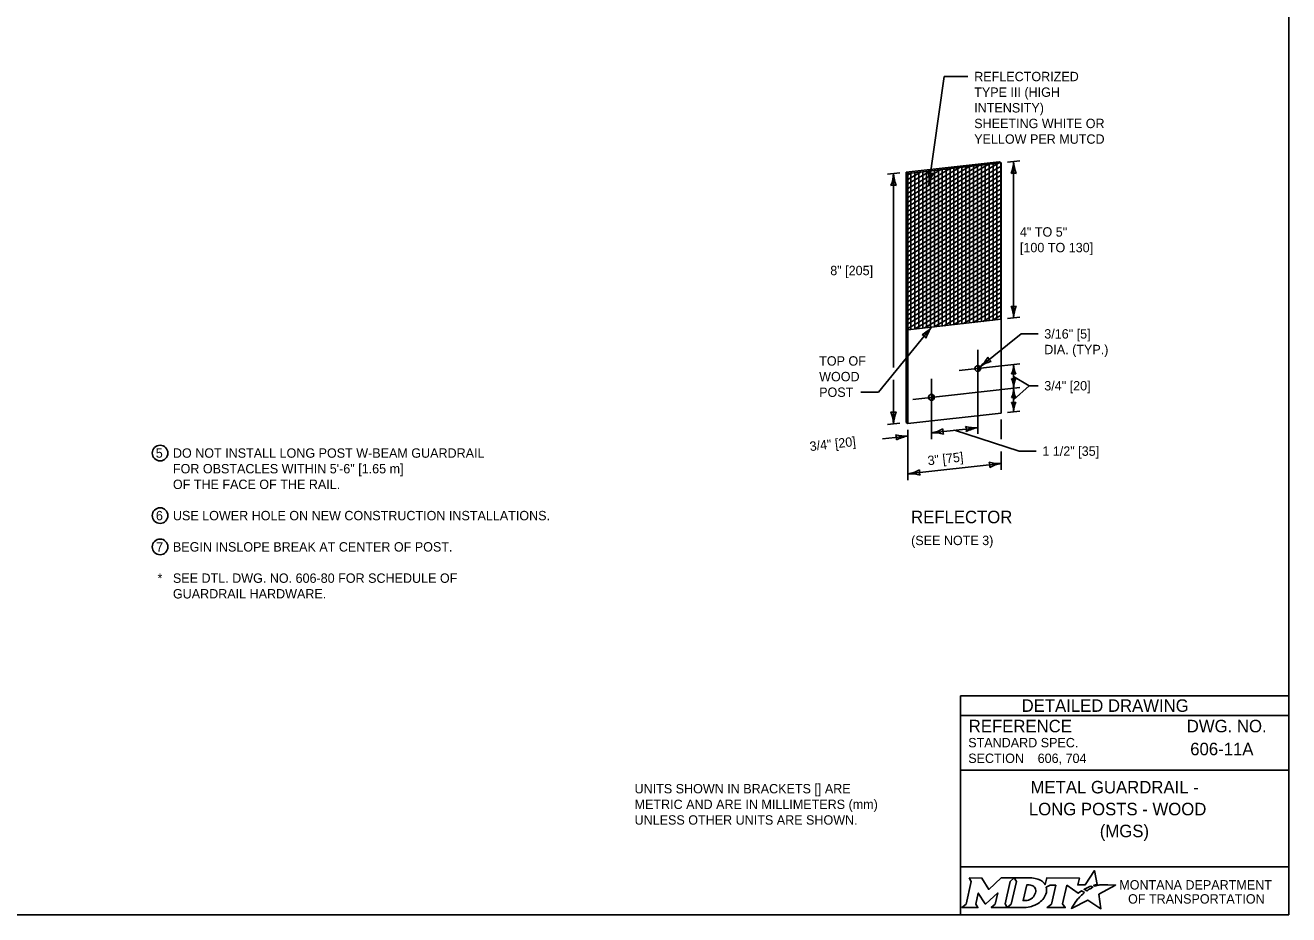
# Model space of a CAD drawing. Extents: x 49991.4 to 50021, y 49987.6 to 50011.4.
# Drawn here: x 50008.67 to 50016.75, y 49987.8 to 49993.49 of the extents above; entities that cross this region are included whole.
import ezdxf

# ---------------------------------------------------------------- set-up
doc = ezdxf.new("R2010")
doc.units = 0
for name, color, linetype in [('Default', 7, 'Continuous'), ('Level 1', 7, 'Continuous'), ('Level 2', 7, 'Continuous'), ('Level 3', 7, 'Continuous'), ('Level 5', 7, 'Continuous')]:
    doc.layers.add(name, color=color, linetype=linetype)

msp = doc.modelspace()

# ---------------------------------------------------------------- linework, layer by layer
at = {"layer": 'Default'}
for points in [[(50014.7056, 49988.0338), (50014.7197, 49988.0104), (50014.6862, 49987.8671), (50014.6605, 49987.8446), (50014.7621, 49987.8446), (50014.7486, 49987.8674), (50014.7648, 49987.9375), (50014.8085, 49987.8685), (50014.8138, 49987.8685), (50014.8889, 49987.938), (50014.8725, 49987.8669), (50014.8478, 49987.8449), (50014.9494, 49987.8449), (50014.9356, 49987.8682), (50014.9688, 49988.0106)], [(50014.9688, 49988.0106), (50014.9941, 49988.0338), (50014.9117, 49988.0338), (50014.8321, 49987.9608), (50014.7876, 49988.0335), (50014.7056, 49988.0338)], [(50015.1077, 49988.0338), (50014.9941, 49988.0338), (50015.0088, 49988.0109), (50014.9749, 49987.8671), (50014.9494, 49987.8449), (50015.06, 49987.8449)], [(50015.5126, 49987.9811), (50015.5023, 49987.9867), (50015.5139, 49987.9895), (50015.5255, 49987.9915), (50015.5081, 49988.0816), (50015.4486, 49987.9903), (50015.4013, 49987.9896), (50015.4116, 49988.0337), (50015.2024, 49988.0338), (50015.1923, 49987.9913), (50015.1865, 49987.9996)], [(50015.1317, 49987.9471), (50015.1305, 49987.939), (50015.1273, 49987.9297), (50015.1231, 49987.9215), (50015.1175, 49987.914), (50015.111, 49987.9071), (50015.1031, 49987.9008), (50015.0948, 49987.8961), (50015.0857, 49987.8922), (50015.0766, 49987.8899), (50015.0674, 49987.889), (50015.0515, 49987.889), (50015.0751, 49987.989), (50015.0911, 49987.989), (50015.0987, 49987.9884), (50015.1063, 49987.9865), (50015.1129, 49987.9835), (50015.119, 49987.9793), (50015.1238, 49987.9743), (50015.1275, 49987.9683), (50015.1302, 49987.9621), (50015.1318, 49987.9547), (50015.1318, 49987.9517), (50015.1317, 49987.9471)], [(50015.1991, 49987.9747), (50015.2237, 49987.9878), (50015.2606, 49987.9878), (50015.232, 49987.8673), (50015.2045, 49987.8446), (50015.3207, 49987.8446), (50015.3037, 49987.8675), (50015.3319, 49987.9877), (50015.4032, 49987.936), (50015.4243, 49987.9511), (50015.444, 49987.9402)], [(50015.3882, 49987.8843), (50015.3729, 49987.8599), (50015.3682, 49987.8524), (50015.3624, 49987.8438), (50015.3601, 49987.8395), (50015.4654, 49987.8926), (50015.5493, 49987.8375), (50015.5362, 49987.9302), (50015.6431, 49987.9886), (50015.5938, 49987.9894), (50015.5637, 49987.9898), (50015.5429, 49987.9901), (50015.5361, 49987.9886), (50015.5312, 49987.9874), (50015.5228, 49987.9851), (50015.5126, 49987.9811)], [(50015.4622, 49987.9535), (50015.4598, 49987.9518), (50015.4415, 49987.9614), (50015.4518, 49987.9671), (50015.4559, 49987.9693), (50015.4645, 49987.9733), (50015.4702, 49987.9759), (50015.4781, 49987.9789), (50015.4854, 49987.9816), (50015.4972, 49987.9742), (50015.4932, 49987.9721), (50015.4886, 49987.9696), (50015.4844, 49987.9674), (50015.4794, 49987.9645), (50015.4775, 49987.9634), (50015.4748, 49987.9618), (50015.4723, 49987.9604), (50015.47, 49987.9588), (50015.4674, 49987.957), (50015.4647, 49987.9552), (50015.4622, 49987.9535)], [(50015.1057, 49987.8522), (50015.1141, 49987.8548), (50015.1271, 49987.8602), (50015.1475, 49987.8712)], [(50015.4021, 49987.9004), (50015.4021, 49987.9004)]]:
    msp.add_lwpolyline(points, dxfattribs=at)
for centre, radius, start, end in [((50015.1308, 49987.9554), 0.0709, 339.53292, 15.85821), ((50015.0868, 49987.9727), 0.1183, 300.91025, 339.13831)]:
    msp.add_arc(centre, radius, start, end, dxfattribs=at)
for centre, major_axis, ratio, start_param, end_param in [((50015.1056, 49987.9864), (0.0834, -0.0037), 0.568097, 0.61298, 1.570796), ((50015.1612, 49987.9937), (0.0361, -0.0295), 0.469099, 1.225588, 1.570796), ((50015.4329, 49987.9305), (-0.0112, -0.0097), 0.021651, 3.157348, 6.283185), ((50015.3952, 49987.8923), (-0.00694, -0.00806), 0.008222, 0, 3.137361), ((50015.4119, 49987.9106), (-0.0098, -0.0102), 0.016458, 3.141593, 6.279097), ((50015.0603, 49987.9932), (0, 0.1484), 0.987302, 3.139398, 3.456847)]:
    msp.add_ellipse(centre, major_axis=major_axis, ratio=ratio, start_param=start_param, end_param=end_param, dxfattribs=at)
at = {"layer": 'Level 1'}
for p, q in [((50014.3025, 49992.5474), (50014.8988, 49992.6139)), ((50014.3151, 49992.5402), (50014.3025, 49992.5474)), ((50014.3025, 49990.9474), (50014.3025, 49992.5474)), ((50014.9114, 49992.6067), (50014.3151, 49992.5402)), ((50014.3151, 49992.2701), (50014.8949, 49992.6048)), ((50014.3151, 49992.2989), (50014.8329, 49992.5979)), ((50014.3151, 49992.3278), (50014.771, 49992.591)), ((50014.3151, 49992.2412), (50014.9114, 49992.5855)), ((50014.3151, 49992.3567), (50014.709, 49992.5841)), ((50014.3151, 49992.3856), (50014.647, 49992.5772)), ((50014.3151, 49992.4144), (50014.585, 49992.5703)), ((50014.3151, 49992.4433), (50014.5231, 49992.5633)), ((50014.3151, 49992.2123), (50014.9114, 49992.5566)), ((50014.3151, 49992.4722), (50014.4611, 49992.5564)), ((50014.3151, 49992.501), (50014.3991, 49992.5495)), ((50014.3842, 49991.5479), (50014.3842, 49992.5479)), ((50014.4092, 49991.5506), (50014.4092, 49992.5506)), ((50014.4342, 49991.5534), (50014.4342, 49992.5534)), ((50014.4592, 49991.5562), (50014.4592, 49992.5562)), ((50014.4842, 49991.559), (50014.4842, 49992.559)), ((50014.5092, 49991.5618), (50014.5092, 49992.5618)), ((50014.5342, 49991.5646), (50014.5342, 49992.5646)), ((50014.5592, 49991.5674), (50014.5592, 49992.5674)), ((50014.5842, 49991.5702), (50014.5842, 49992.5702)), ((50014.6092, 49991.573), (50014.6092, 49992.573)), ((50014.6342, 49991.5757), (50014.6342, 49992.5757)), ((50014.6592, 49991.5785), (50014.6592, 49992.5785)), ((50014.6842, 49991.5813), (50014.6842, 49992.5813)), ((50014.7092, 49991.5841), (50014.7092, 49992.5841)), ((50014.7342, 49991.5869), (50014.7342, 49992.5869)), ((50014.7592, 49991.5897), (50014.7592, 49992.5897)), ((50014.7842, 49991.5925), (50014.7842, 49992.5925)), ((50014.8092, 49991.5953), (50014.8092, 49992.5953)), ((50014.8342, 49991.5981), (50014.8342, 49992.5981)), ((50014.8592, 49991.6008), (50014.8592, 49992.6008)), ((50014.8842, 49991.6036), (50014.8842, 49992.6036)), ((50014.9114, 49992.6067), (50014.8988, 49992.6139)), ((50014.9092, 49991.6064), (50014.9092, 49992.6064)), ((50014.9114, 49991.6067), (50014.9114, 49992.6067)), ((50014.3151, 49992.5299), (50014.3371, 49992.5426)), ((50014.3151, 49992.5402), (50014.3151, 49991.5402)), ((50014.3151, 49992.1835), (50014.9114, 49992.5278)), ((50014.3151, 49992.1546), (50014.9114, 49992.4989)), ((50014.3151, 49992.1257), (50014.9114, 49992.47)), ((50014.3342, 49991.5423), (50014.3342, 49992.5423)), ((50014.3592, 49991.5451), (50014.3592, 49992.5451)), ((50014.3151, 49992.0969), (50014.9114, 49992.4412)), ((50014.3151, 49992.068), (50014.9114, 49992.4123)), ((50014.3151, 49992.0391), (50014.9114, 49992.3834)), ((50014.3151, 49992.0103), (50014.9114, 49992.3545)), ((50014.3151, 49991.9814), (50014.9114, 49992.3257)), ((50014.3151, 49991.9525), (50014.9114, 49992.2968)), ((50014.3151, 49991.9237), (50014.9114, 49992.2679)), ((50014.3151, 49991.8948), (50014.9114, 49992.2391)), ((50014.3151, 49991.8659), (50014.9114, 49992.2102)), ((50014.3151, 49991.8371), (50014.9114, 49992.1813)), ((50014.3151, 49991.8082), (50014.9114, 49992.1525)), ((50014.3151, 49991.7793), (50014.9114, 49992.1236)), ((50014.3151, 49991.7505), (50014.9114, 49992.0947)), ((50014.3151, 49991.7216), (50014.9114, 49992.0659)), ((50014.3151, 49991.6927), (50014.9114, 49992.037)), ((50014.3151, 49991.6639), (50014.9114, 49992.0081)), ((50014.3151, 49991.635), (50014.9114, 49991.9793)), ((50014.3151, 49991.6061), (50014.9114, 49991.9504)), ((50014.3151, 49991.5773), (50014.9114, 49991.9215)), ((50014.3151, 49991.5484), (50014.9114, 49991.8927)), ((50014.3594, 49991.5451), (50014.9114, 49991.8638)), ((50014.4214, 49991.552), (50014.9114, 49991.8349)), ((50014.4833, 49991.5589), (50014.9114, 49991.8061)), ((50014.5453, 49991.5658), (50014.9114, 49991.7772)), ((50014.6073, 49991.5727), (50014.9114, 49991.7483)), ((50014.6693, 49991.5797), (50014.9114, 49991.7195)), ((50014.7312, 49991.5866), (50014.9114, 49991.6906)), ((50014.7932, 49991.5935), (50014.9114, 49991.6617)), ((50014.3151, 49991.5402), (50014.9114, 49991.6067)), ((50014.8552, 49991.6004), (50014.9114, 49991.6329)), ((50014.9114, 49991.0067), (50014.9114, 49991.6067)), ((50014.3151, 49990.9402), (50014.3151, 49991.5402)), ((50014.3151, 49990.9402), (50014.3025, 49990.9474)), ((50014.3151, 49990.9402), (50014.9114, 49991.0067))]:
    msp.add_line(p, q, dxfattribs=at)
msp.add_lwpolyline([(49999.3835, 49998.9992), (50016.7501, 49998.9992), (50016.7501, 49987.7988), (49999.3835, 49987.7988)], close=True, dxfattribs=at)
for centre in [(50014.7614, 49991.2918), (50014.4651, 49991.1078)]:
    msp.add_circle(centre, 0.0187, dxfattribs=at)
for centre, start, end in [((50014.7534, 49991.2916), 283.93324, 79.31293), ((50014.4563, 49991.1077), 284.06296, 76.81783)]:
    msp.add_arc(centre, 0.0187, start, end, dxfattribs=at)
at = {"layer": 'Level 2'}
for centre in [(50009.5323, 49990.7514), (50009.5323, 49990.3514), (50009.5323, 49990.1514)]:
    msp.add_circle(centre, 0.05, dxfattribs=at)
at = {"layer": 'Level 3'}
for p, q in [((50014.5467, 49993.1594), (50014.4481, 49992.4669)), ((50014.6987, 49993.1594), (50014.5467, 49993.1594)), ((50014.9512, 49992.6111), (50015.0307, 49992.62)), ((50014.9909, 49992.6155), (50014.9909, 49991.6155)), ((50014.1833, 49992.5341), (50014.2628, 49992.543)), ((50014.223, 49992.5386), (50014.223, 49991.2991)), ((50014.9512, 49991.6111), (50015.0307, 49991.62)), ((50014.1264, 49991.1405), (50014.4656, 49991.5569)), ((50015.0393, 49991.5135), (50014.7762, 49991.3034)), ((50015.0393, 49991.5135), (50015.1467, 49991.5135)), ((50014.9909, 49991.3174), (50014.9909, 49991.1665)), ((50014.223, 49991.2191), (50014.223, 49990.9386)), ((50015.0905, 49991.1818), (50014.9909, 49991.2419)), ((50015.0905, 49991.1818), (50014.9909, 49991.091)), ((50015.0905, 49991.1818), (50015.1467, 49991.1818)), ((50014.0133, 49991.1405), (50014.1264, 49991.1405)), ((50014.9909, 49991.1665), (50014.9909, 49991.0155)), ((50014.9512, 49991.0111), (50015.0307, 49991.02)), ((50014.1833, 49990.9341), (50014.2628, 49990.943)), ((50014.9114, 49990.9666), (50014.9114, 49990.8411)), ((50014.1518, 49990.8419), (50014.3151, 49990.8601)), ((50014.3151, 49990.9001), (50014.3151, 49990.5782)), ((50014.4651, 49990.8804), (50014.7614, 49990.9135)), ((50015.0271, 49990.7638), (50014.6133, 49990.897)), ((50014.9114, 49990.7611), (50014.9114, 49990.6447)), ((50015.0271, 49990.7638), (50015.1345, 49990.7638)), ((50014.9114, 49990.6847), (50014.3151, 49990.6182))]:
    msp.add_line(p, q, dxfattribs=at)
for centre, radius, start, end in [((50014.7688, 49992.6247), 0.2223, 337.45601, 357.63952), ((50015.2236, 49992.627), 0.233, 182.82731, 202.07716), ((50014.0009, 49992.5477), 0.2223, 337.45601, 357.63952), ((50014.223, 49992.4103), 0.0548, 72.13882, 107.86118), ((50014.4557, 49992.55), 0.233, 182.82731, 202.07716), ((50014.4708, 49992.5931), 0.0548, 241.94593, 277.66829), ((50014.217, 49992.4968), 0.233, 352.63442, 11.88427), ((50014.6651, 49992.4186), 0.2223, 147.26312, 167.44663), ((50014.9909, 49992.4873), 0.0548, 72.13882, 107.86118), ((50014.9909, 49991.7438), 0.0548, 252.13882, 287.86118), ((50014.7582, 49991.604), 0.233, 2.82731, 22.07716), ((50015.213, 49991.6064), 0.2223, 157.45601, 177.63952), ((50014.2978, 49991.7028), 0.2223, 298.82131, 319.00482), ((50014.3855, 49991.4568), 0.0548, 33.50412, 69.22648), ((50014.6545, 49991.4206), 0.233, 144.19261, 163.44246), ((50014.6233, 49991.4792), 0.233, 310.99921, 330.24906), ((50014.9062, 49991.1231), 0.2223, 105.62791, 125.81142), ((50014.877, 49991.3826), 0.0548, 200.31072, 236.03308), ((50014.8132, 49991.3247), 0.1779, 337.45601, 357.63952), ((50014.9909, 49991.2148), 0.0438, 72.13882, 107.86118), ((50015.1771, 49991.3266), 0.1864, 182.82731, 202.07716), ((50014.9909, 49991.269), 0.0438, 252.13882, 287.86118), ((50014.8047, 49991.1573), 0.1864, 2.82731, 22.07716), ((50015.1686, 49991.1591), 0.1779, 157.45601, 177.63952), ((50014.8132, 49991.1738), 0.1779, 337.45601, 357.63952), ((50014.9909, 49991.0639), 0.0438, 72.13882, 107.86118), ((50015.1771, 49991.1757), 0.1864, 182.82731, 202.07716), ((50014.223, 49991.0668), 0.0548, 252.13882, 287.86118), ((50013.9903, 49990.9271), 0.233, 2.82731, 22.07716), ((50014.4451, 49990.9294), 0.2223, 157.45601, 177.63952), ((50014.9909, 49991.1181), 0.0438, 252.13882, 287.86118), ((50014.8047, 49991.0063), 0.1864, 2.82731, 22.07716), ((50015.1686, 49991.0082), 0.1779, 157.45601, 177.63952), ((50014.2996, 49991.0819), 0.2223, 253.82131, 274.00482), ((50014.1877, 49990.8459), 0.0548, 348.50412, 24.22648), ((50014.3523, 49990.6301), 0.233, 99.19261, 118.44246), ((50014.4279, 49991.1104), 0.233, 279.19261, 298.44246), ((50014.4806, 49990.6587), 0.2223, 73.82131, 94.00482), ((50014.5925, 49990.8947), 0.0548, 168.50412, 204.22648), ((50014.7459, 49991.1353), 0.2223, 253.82131, 274.00482), ((50014.634, 49990.8993), 0.0548, 348.50412, 24.22648), ((50014.7986, 49990.6835), 0.233, 99.19261, 118.44246), ((50014.8959, 49990.9065), 0.2223, 253.82131, 274.00482), ((50014.784, 49990.6705), 0.0548, 348.50412, 24.22648), ((50014.2779, 49990.8482), 0.233, 279.19261, 298.44246), ((50014.3306, 49990.3964), 0.2223, 73.82131, 94.00482), ((50014.4425, 49990.6324), 0.0548, 168.50412, 204.22648), ((50014.9486, 49990.4547), 0.233, 99.19261, 118.44246)]:
    msp.add_arc(centre, radius, start, end, dxfattribs=at)
at = {"layer": 'Level 5'}
for p, q in [((50014.7614, 49990.8735), (50014.7614, 49991.4105)), ((50014.6428, 49991.2786), (50015.0307, 49991.3218)), ((50014.4651, 49990.8404), (50014.4651, 49991.2266)), ((50014.3465, 49991.0946), (50015.0307, 49991.1709)), ((50016.7501, 49989.1988), (50014.6501, 49989.1988)), ((50014.6501, 49989.1988), (50014.6501, 49987.7988)), ((50016.7501, 49989.0738), (50014.6501, 49989.0738)), ((50016.3862, 49988.8587), (50016.3862, 49988.8587)), ((50015.1444, 49988.7993), (50015.1444, 49988.7993)), ((50016.7501, 49988.7238), (50014.6501, 49988.7238)), ((50015.7001, 49988.4747), (50015.7001, 49988.4747)), ((50016.7501, 49988.1057), (50014.6501, 49988.1057))]:
    msp.add_line(p, q, dxfattribs=at)

# ---------------------------------------------------------------- texts
at = {"layer": 'Default'}
for s, p in [('MONTANA DEPARTMENT', (50015.6663, 49987.96)), ('OF TRANSPORTATION', (50015.7225, 49987.87))]:
    msp.add_text(s, height=0.06, dxfattribs=at).set_placement(p)
at = {"layer": 'Level 2'}
for s, height, p in [('REFLECTORIZED ', 0.06, (50014.7387, 49993.1294)), ('TYPE III (HIGH', 0.06, (50014.7387, 49993.0294)), ('INTENSITY)', 0.06, (50014.7387, 49992.9294)), ('SHEETING WHITE OR', 0.06, (50014.7387, 49992.8294)), ('YELLOW PER MUTCD', 0.06, (50014.7387, 49992.7294)), ('4" TO 5" ', 0.06, (50015.0309, 49992.1355)), ('[100 TO 130]', 0.06, (50015.0309, 49992.0355)), ('8" [205]', 0.06, (50013.818, 49991.8888)), ('3/16" [5]', 0.06, (50015.1867, 49991.4835)), ('DIA. (TYP.)', 0.06, (50015.1867, 49991.3835)), ('TOP OF ', 0.06, (50013.7471, 49991.3105)), ('WOOD ', 0.06, (50013.7471, 49991.2105)), ('3/4" [20]', 0.06, (50015.1867, 49991.1518)), ('POST', 0.06, (50013.7471, 49991.1105)), ('5', 0.06, (50009.5046, 49990.7214)), ('DO NOT INSTALL LONG POST W-BEAM GUARDRAIL', 0.06, (50009.6141, 49990.7214)), ('FOR OBSTACLES WITHIN 5\'-6" [1.65 m]  ', 0.06, (50009.6141, 49990.6214)), ('OF THE FACE OF THE RAIL.', 0.06, (50009.6141, 49990.5214)), ('6', 0.06, (50009.5054, 49990.3214)), ('USE LOWER HOLE ON NEW CONSTRUCTION INSTALLATIONS.', 0.06, (50009.6141, 49990.3214)), ('REFLECTOR', 0.08, (50014.3347, 49990.3026)), ('(SEE NOTE 3)', 0.06, (50014.3351, 49990.1626)), ('7', 0.06, (50009.5071, 49990.1214)), ('BEGIN INSLOPE BREAK AT CENTER OF POST.', 0.06, (50009.6141, 49990.1214)), ('*', 0.06, (50009.5155, 49989.9214)), ('SEE DTL. DWG. NO. 606-80 FOR SCHEDULE OF ', 0.06, (50009.6141, 49989.9214)), ('GUARDRAIL HARDWARE.', 0.06, (50009.6141, 49989.8214)), ('606, 704', 0.06, (50015.1444, 49988.7693)), ('606-11A', 0.08, (50016.1201, 49988.8187)), ('UNITS SHOWN IN BRACKETS [] ARE ', 0.06, (50012.5665, 49988.5749)), ('METAL GUARDRAIL -', 0.08, (50015.0988, 49988.5747)), ('METRIC AND ARE IN MILLIMETERS (mm) ', 0.06, (50012.5665, 49988.4749)), ('LONG POSTS - WOOD ', 0.08, (50015.0881, 49988.4347)), ('UNLESS OTHER UNITS ARE SHOWN.', 0.06, (50012.5665, 49988.3749)), ('(MGS)', 0.08, (50015.5417, 49988.2947))]:
    msp.add_text(s, height=height, dxfattribs=at).set_placement(p)
for s, rotation, p in [(' 3/4" [20]', 6.3653, (50013.6675, 49990.7613)), ('1 1/2" [35]', 360, (50015.1745, 49990.7338)), ('3" [75]', 6.3563, (50014.4441, 49990.6728))]:
    msp.add_text(s, height=0.06, rotation=rotation, dxfattribs=at).set_placement(p)
at = {"layer": 'Level 5'}
for s, height, p in [('DETAILED DRAWING', 0.0799, (50015.0418, 49989.0963)), ('REFERENCE', 0.08, (50014.7037, 49988.9654)), ('DWG. NO.', 0.08, (50016.0979, 49988.9654)), ('STANDARD SPEC.', 0.06, (50014.7004, 49988.8694)), ('SECTION', 0.06, (50014.7004, 49988.7694))]:
    msp.add_text(s, height=height, dxfattribs=at).set_placement(p)

doc.saveas('drawing.dxf')
